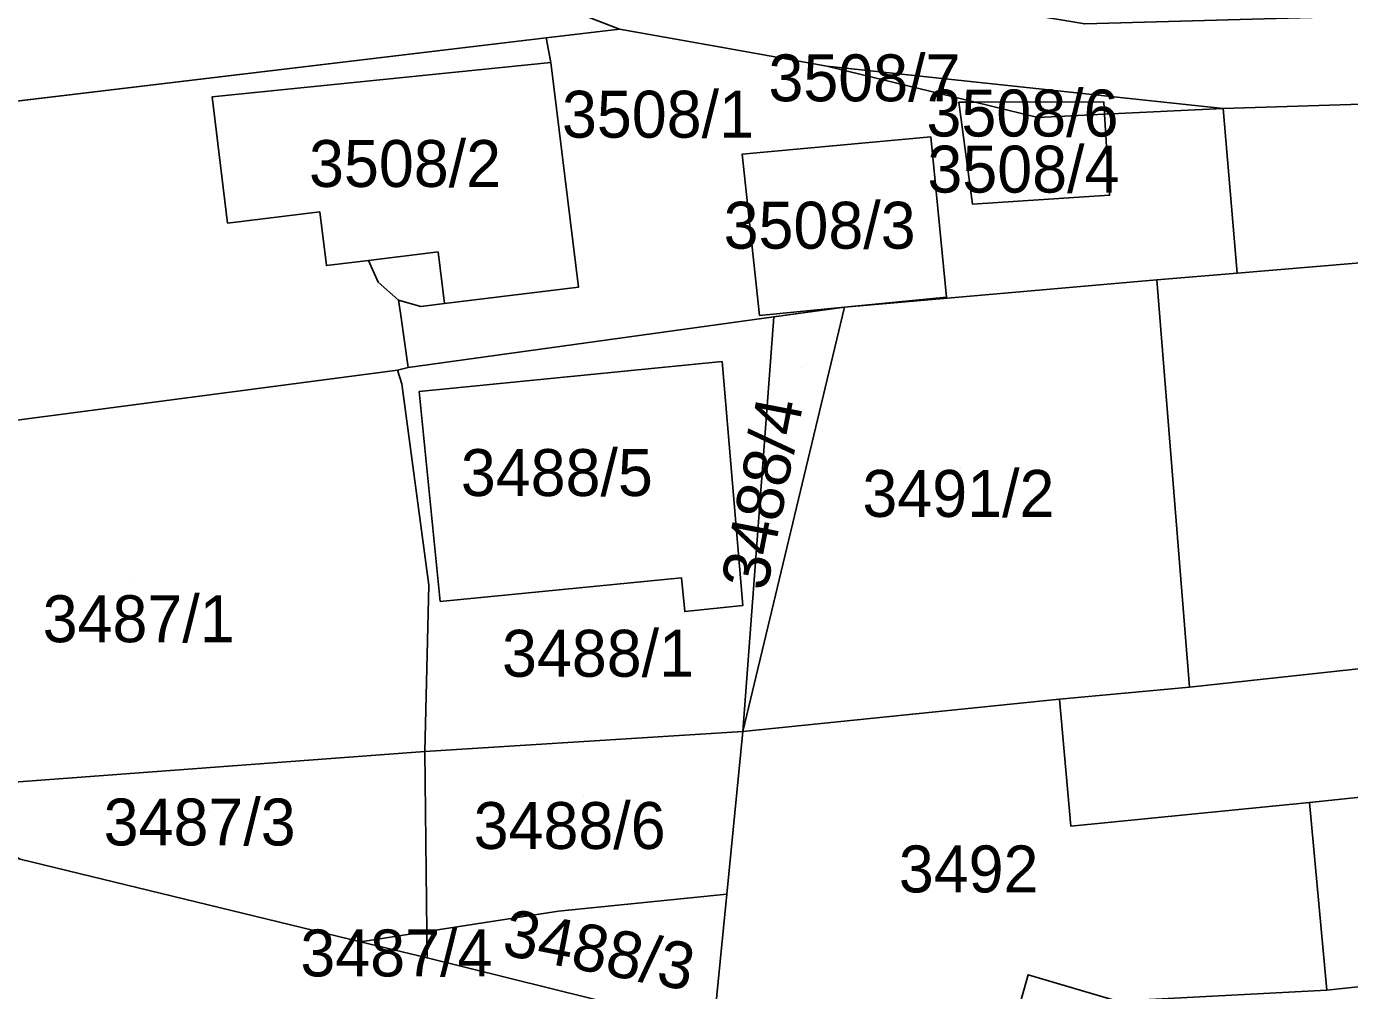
# Model space of a CAD drawing. Extents: x -262657 to -261595, y -1238015 to -1237156.
# Drawn here: x -262217.3 to -262160.9, y -1237493.9 to -1237452.8 of the extents above; entities that cross this region are included whole.
import ezdxf

# ---------------------------------------------------------------- set-up
doc = ezdxf.new("R2010")
doc.units = 0
for name, color, linetype in [('body_kn', 7, 'Continuous'), ('kladpar_druhypozemkov', 7, 'Continuous'), ('kladpar_hranice', 7, 'Continuous'), ('kladpar_parcelnecisla', 7, 'Continuous'), ('kladpar_plochy', 7, 'Continuous'), ('zappar_hrandruhpozemk', 7, 'Continuous')]:
    doc.layers.add(name, color=color, linetype=linetype)

msp = doc.modelspace()

# ---------------------------------------------------------------- linework, layer by layer
at = {"layer": 'body_kn'}
for p, q in [((-262192.05, -1237452.94), (-262192.05, -1237452.94)), ((-262195.18, -1237453.31), (-262195.18, -1237453.31)), ((-262195.18, -1237453.31), (-262195.18, -1237453.31)), ((-262187.73, -1237453.71), (-262187.73, -1237453.71)), ((-262194.98, -1237454.37), (-262194.98, -1237454.37)), ((-262194.98, -1237454.37), (-262194.98, -1237454.37)), ((-262183.22, -1237454.52), (-262183.22, -1237454.52)), ((-262183.22, -1237454.52), (-262183.22, -1237454.52)), ((-262209.41, -1237455.83), (-262209.41, -1237455.83)), ((-262177.59, -1237456.06), (-262177.59, -1237456.06)), ((-262177.59, -1237456.06), (-262177.59, -1237456.06)), ((-262176.89, -1237456.06), (-262176.89, -1237456.06)), ((-262171.42, -1237456.04), (-262171.42, -1237456.04)), ((-262171.42, -1237456.04), (-262171.42, -1237456.04)), ((-262171.39, -1237456.57), (-262171.39, -1237456.57)), ((-262166.33, -1237456.32), (-262166.33, -1237456.32)), ((-262166.33, -1237456.32), (-262166.33, -1237456.32)), ((-262174.23, -1237456.71), (-262174.23, -1237456.71)), ((-262178.78, -1237457.54), (-262178.78, -1237457.54)), ((-262186.82, -1237458.27), (-262186.82, -1237458.27)), ((-262186.82, -1237458.27), (-262186.82, -1237458.27)), ((-262171.17, -1237460.02), (-262171.17, -1237460.02)), ((-262177.01, -1237460.4), (-262177.01, -1237460.4)), ((-262204.82, -1237460.73), (-262204.82, -1237460.73)), ((-262208.75, -1237461.21), (-262208.75, -1237461.21)), ((-262202.75, -1237462.81), (-262202.75, -1237462.81)), ((-262202.75, -1237462.81), (-262202.75, -1237462.81)), ((-262199.77, -1237462.44), (-262199.77, -1237462.44)), ((-262204.54, -1237463.02), (-262204.54, -1237463.02)), ((-262165.74, -1237463.34), (-262165.74, -1237463.34)), ((-262202.33, -1237463.73), (-262202.33, -1237463.73)), ((-262193.8, -1237463.94), (-262193.8, -1237463.94)), ((-262169.15, -1237463.63), (-262169.15, -1237463.63)), ((-262201.46, -1237464.49), (-262201.46, -1237464.49)), ((-262178.12, -1237464.37), (-262178.12, -1237464.37)), ((-262201.38, -1237465.05), (-262201.38, -1237465.05)), ((-262200.52, -1237464.76), (-262200.52, -1237464.76)), ((-262199.5, -1237464.63), (-262199.5, -1237464.63)), ((-262182.46, -1237464.79), (-262182.46, -1237464.79)), ((-262182.46, -1237464.79), (-262182.46, -1237464.79)), ((-262186.08, -1237465.14), (-262186.08, -1237465.14)), ((-262185.48, -1237465.21), (-262185.48, -1237465.21)), ((-262201.05, -1237467.36), (-262201.05, -1237467.36)), ((-262187.68, -1237467.11), (-262187.68, -1237467.11)), ((-262201.51, -1237467.47), (-262201.51, -1237467.47)), ((-262201.51, -1237467.47), (-262201.51, -1237467.47)), ((-262201.33, -1237468.06), (-262201.33, -1237468.06)), ((-262200.58, -1237468.39), (-262200.58, -1237468.39)), ((-262189.41, -1237476.32), (-262189.41, -1237476.32)), ((-262200.18, -1237476.64), (-262200.18, -1237476.64)), ((-262199.69, -1237477.34), (-262199.69, -1237477.34)), ((-262199.69, -1237477.34), (-262199.69, -1237477.34)), ((-262186.8, -1237477.51), (-262186.8, -1237477.51)), ((-262189.27, -1237477.76), (-262189.27, -1237477.76)), ((-262167.76, -1237480.98), (-262167.76, -1237480.98)), ((-262173.3, -1237481.5), (-262173.3, -1237481.5)), ((-262186.79, -1237482.88), (-262186.79, -1237482.88)), ((-262186.79, -1237482.88), (-262186.79, -1237482.88)), ((-262200.34, -1237483.73), (-262200.34, -1237483.73)), ((-262162.65, -1237485.9), (-262162.65, -1237485.9)), ((-262172.82, -1237486.91), (-262172.82, -1237486.91)), ((-262187.47, -1237489.81), (-262187.47, -1237489.81)), ((-262194.65, -1237490.53), (-262194.65, -1237490.53)), ((-262194.65, -1237490.53), (-262194.65, -1237490.53)), ((-262200.26, -1237491.4), (-262200.26, -1237491.4)), ((-262203.08, -1237491.83), (-262203.08, -1237491.83)), ((-262203.08, -1237491.83), (-262203.08, -1237491.83)), ((-262200.25, -1237492.52), (-262200.25, -1237492.52)), ((-262174.64, -1237493.24), (-262174.64, -1237493.24)), ((-262161.92, -1237493.89), (-262161.92, -1237493.89)), ((-262161.92, -1237493.89), (-262161.92, -1237493.89))]:
    msp.add_line(p, q, dxfattribs=at)
at = {"layer": 'kladpar_druhypozemkov'}
for p, q in [((-262180.68, -1237454.95), (-262180.68, -1237454.95)), ((-262190.66, -1237456.11), (-262190.66, -1237456.11)), ((-262173.99, -1237456.3), (-262173.99, -1237456.3)), ((-262200.34, -1237457.91), (-262200.34, -1237457.91)), ((-262174.07, -1237458.24), (-262174.07, -1237458.24)), ((-262182.44, -1237460.43), (-262182.44, -1237460.43)), ((-262184.29, -1237467.37), (-262184.29, -1237467.37)), ((-262193.73, -1237470.88), (-262193.73, -1237470.88)), ((-262177.53, -1237471.67), (-262177.53, -1237471.67)), ((-262212.93, -1237476.36), (-262212.93, -1237476.36)), ((-262192.96, -1237478.63), (-262192.96, -1237478.63)), ((-262193.58, -1237485.59), (-262193.58, -1237485.59)), ((-262209.51, -1237486.32), (-262209.51, -1237486.32)), ((-262177.09, -1237488.16), (-262177.09, -1237488.16)), ((-262201.44, -1237491.98), (-262201.44, -1237491.98)), ((-262192.56, -1237491.88), (-262192.56, -1237491.88))]:
    msp.add_line(p, q, dxfattribs=at)
at = {"layer": 'kladpar_hranice'}
for p, q in [((-262183.22, -1237454.52), (-262166.33, -1237456.32)), ((-262176.89, -1237456.06), (-262183.22, -1237454.52)), ((-262183.22, -1237454.52), (-262176.89, -1237456.06)), ((-262177.59, -1237456.06), (-262176.89, -1237456.06)), ((-262176.89, -1237456.06), (-262171.42, -1237456.04)), ((-262171.42, -1237456.04), (-262171.39, -1237456.57)), ((-262166.33, -1237456.32), (-262171.39, -1237456.57)), ((-262171.39, -1237456.57), (-262166.33, -1237456.32))]:
    msp.add_line(p, q, dxfattribs=at)
for points in [[(-262230.34, -1237434.19), (-262221.46, -1237439.3), (-262209.51, -1237446.2), (-262192.05, -1237452.94), (-262195.18, -1237453.31), (-262242.2, -1237458.94), (-262242.94, -1237448.59), (-262237.36, -1237447.78), (-262237.65, -1237443.96)], [(-262137.3, -1237455.41), (-262166.33, -1237456.32), (-262183.22, -1237454.52), (-262187.73, -1237453.71), (-262192.05, -1237452.94), (-262209.51, -1237446.2), (-262221.46, -1237439.3), (-262220.93, -1237439.31), (-262218, -1237436.69), (-262214.52, -1237438.44), (-262207.07, -1237441.9), (-262193.17, -1237448.01), (-262184.15, -1237450.78), (-262180.7, -1237451.3), (-262172.23, -1237452.72), (-262144.2, -1237451.94)], [(-262195.18, -1237453.31), (-262192.05, -1237452.94), (-262187.73, -1237453.71), (-262183.22, -1237454.52)], [(-262254.6, -1237460.42), (-262242.2, -1237458.94), (-262195.18, -1237453.31), (-262194.98, -1237454.37), (-262209.41, -1237455.83), (-262208.75, -1237461.21), (-262204.82, -1237460.73), (-262204.54, -1237463.02), (-262202.75, -1237462.81), (-262202.33, -1237463.73), (-262201.46, -1237464.49), (-262201.38, -1237465.05), (-262201.05, -1237467.36), (-262201.51, -1237467.47), (-262251.24, -1237474.01), (-262254.6, -1237460.42)], [(-262185.48, -1237465.21), (-262201.05, -1237467.36), (-262201.38, -1237465.05), (-262201.46, -1237464.49), (-262200.52, -1237464.76), (-262199.5, -1237464.63), (-262193.8, -1237463.94), (-262194.98, -1237454.37), (-262195.18, -1237453.31)], [(-262194.98, -1237454.37), (-262193.8, -1237463.94), (-262199.5, -1237464.63), (-262200.52, -1237464.76), (-262201.46, -1237464.49), (-262202.33, -1237463.73), (-262202.75, -1237462.81), (-262204.54, -1237463.02), (-262204.82, -1237460.73), (-262208.75, -1237461.21), (-262209.41, -1237455.83), (-262194.98, -1237454.37)], [(-262166.33, -1237456.32), (-262137.3, -1237455.41), (-262124.74, -1237457.28), (-262120.3, -1237459.49), (-262143.93, -1237461.51), (-262165.74, -1237463.34), (-262166.33, -1237456.32)], [(-262171.39, -1237456.57), (-262171.17, -1237460.02), (-262177.01, -1237460.4), (-262177.59, -1237456.06)], [(-262176.89, -1237456.06), (-262177.59, -1237456.06), (-262177.01, -1237460.4), (-262171.17, -1237460.02), (-262171.39, -1237456.57)], [(-262171.39, -1237456.57), (-262171.42, -1237456.04), (-262176.89, -1237456.06)], [(-262171.39, -1237456.57), (-262174.23, -1237456.71), (-262176.89, -1237456.06)], [(-262176.89, -1237456.06), (-262174.23, -1237456.71), (-262171.39, -1237456.57)], [(-262166.33, -1237456.32), (-262165.74, -1237463.34), (-262169.15, -1237463.63), (-262182.46, -1237464.79), (-262185.48, -1237465.21)], [(-262186.82, -1237458.27), (-262178.78, -1237457.54), (-262178.12, -1237464.37), (-262182.46, -1237464.79), (-262186.08, -1237465.14), (-262186.82, -1237458.27)], [(-262186.08, -1237465.14), (-262182.46, -1237464.79), (-262178.12, -1237464.37), (-262178.78, -1237457.54), (-262186.82, -1237458.27), (-262186.08, -1237465.14)], [(-262135.5, -1237477.53), (-262159, -1237480.03), (-262167.76, -1237480.98), (-262169.15, -1237463.63), (-262165.74, -1237463.34), (-262143.93, -1237461.51), (-262143.12, -1237468.01), (-262138.13, -1237467.57), (-262137.27, -1237475.95), (-262135.55, -1237475.84), (-262135.51, -1237477.18), (-262135.5, -1237477.53)], [(-262182.46, -1237464.79), (-262169.15, -1237463.63), (-262167.76, -1237480.98), (-262173.3, -1237481.5), (-262186.79, -1237482.88), (-262182.46, -1237464.79)], [(-262186.79, -1237482.88), (-262185.48, -1237465.21), (-262182.46, -1237464.79), (-262186.79, -1237482.88)], [(-262201.51, -1237467.47), (-262201.05, -1237467.36), (-262185.48, -1237465.21), (-262186.79, -1237482.88), (-262200.34, -1237483.73)], [(-262199.69, -1237477.34), (-262200.58, -1237468.39), (-262187.68, -1237467.11), (-262186.8, -1237477.51), (-262189.27, -1237477.76), (-262189.41, -1237476.32), (-262199.69, -1237477.34)], [(-262199.69, -1237477.34), (-262189.41, -1237476.32), (-262189.27, -1237477.76), (-262186.8, -1237477.51), (-262187.68, -1237467.11), (-262200.58, -1237468.39), (-262199.69, -1237477.34)], [(-262227.97, -1237485.78), (-262233.77, -1237484.32), (-262249.82, -1237480.64), (-262251.24, -1237474.01), (-262201.51, -1237467.47), (-262201.33, -1237468.06), (-262200.18, -1237476.64), (-262200.34, -1237483.73), (-262222.8, -1237485.4), (-262227.97, -1237485.78)], [(-262200.34, -1237483.73), (-262200.18, -1237476.64), (-262201.33, -1237468.06), (-262201.51, -1237467.47)], [(-262100.07, -1237473.74), (-262098.36, -1237475.95), (-262108.93, -1237477.01), (-262108.19, -1237482.75), (-262110.64, -1237482.99), (-262139.61, -1237485.8), (-262139.74, -1237483.44), (-262150.33, -1237484.6), (-262162.65, -1237485.9), (-262172.82, -1237486.91), (-262173.3, -1237481.5), (-262167.76, -1237480.98), (-262159, -1237480.03), (-262135.5, -1237477.53), (-262127.63, -1237476.72), (-262121.33, -1237476.07), (-262111.63, -1237475.04), (-262100.07, -1237473.74)], [(-262176.23, -1237498.85), (-262188.04, -1237495.55), (-262187.47, -1237489.81), (-262186.79, -1237482.88), (-262173.3, -1237481.5), (-262172.82, -1237486.91), (-262162.65, -1237485.9), (-262161.92, -1237493.89), (-262170.83, -1237494.36), (-262174.64, -1237493.24), (-262176.23, -1237498.85)], [(-262194.65, -1237490.53), (-262200.26, -1237491.4), (-262200.34, -1237483.73), (-262186.79, -1237482.88), (-262187.47, -1237489.81), (-262194.65, -1237490.53)], [(-262203.08, -1237491.83), (-262217.58, -1237488.31), (-262222.8, -1237485.4), (-262200.34, -1237483.73), (-262200.26, -1237491.4), (-262203.08, -1237491.83)], [(-262154.86, -1237504.09), (-262172.44, -1237499.78), (-262176.23, -1237498.85), (-262174.64, -1237493.24), (-262170.83, -1237494.36), (-262161.92, -1237493.89), (-262162.65, -1237485.9), (-262150.33, -1237484.6), (-262139.74, -1237483.44), (-262139.61, -1237485.8), (-262139.16, -1237493.69), (-262154.25, -1237495.79), (-262154.86, -1237504.09)], [(-262233.77, -1237484.32), (-262227.97, -1237485.78), (-262217.58, -1237488.31), (-262203.08, -1237491.83), (-262200.25, -1237492.52), (-262188.04, -1237495.55), (-262176.23, -1237498.85), (-262172.44, -1237499.78), (-262154.86, -1237504.09), (-262127.96, -1237510.84), (-262123.16, -1237511.93), (-262108.89, -1237515.33), (-262096.16, -1237518.4), (-262086.35, -1237520.76), (-262075.41, -1237523.56), (-262071.48, -1237524.52), (-262067.34, -1237525.53), (-262049.86, -1237529.82), (-262034.62, -1237534.07), (-262030.05, -1237535.39)], [(-262188.04, -1237495.55), (-262200.25, -1237492.52), (-262200.26, -1237491.4), (-262194.65, -1237490.53), (-262187.47, -1237489.81), (-262188.04, -1237495.55)], [(-262203.08, -1237491.83), (-262200.26, -1237491.4), (-262200.25, -1237492.52), (-262203.08, -1237491.83)]]:
    msp.add_lwpolyline(points, dxfattribs=at)
at = {"layer": 'kladpar_plochy'}
for p, q in [((-262209.51, -1237446.2), (-262192.05, -1237452.94)), ((-262192.05, -1237452.94), (-262195.18, -1237453.31)), ((-262195.18, -1237453.31), (-262192.05, -1237452.94)), ((-262192.05, -1237452.94), (-262187.73, -1237453.71)), ((-262195.18, -1237453.31), (-262242.2, -1237458.94)), ((-262194.98, -1237454.37), (-262195.18, -1237453.31)), ((-262187.73, -1237453.71), (-262183.22, -1237454.52)), ((-262193.8, -1237463.94), (-262194.98, -1237454.37)), ((-262183.22, -1237454.52), (-262176.89, -1237456.06)), ((-262176.89, -1237456.06), (-262177.59, -1237456.06)), ((-262177.59, -1237456.06), (-262177.01, -1237460.4)), ((-262171.39, -1237456.57), (-262166.33, -1237456.32)), ((-262171.17, -1237460.02), (-262171.39, -1237456.57)), ((-262166.33, -1237456.32), (-262165.74, -1237463.34)), ((-262178.78, -1237457.54), (-262186.82, -1237458.27)), ((-262178.12, -1237464.37), (-262178.78, -1237457.54)), ((-262186.82, -1237458.27), (-262186.08, -1237465.14)), ((-262177.01, -1237460.4), (-262171.17, -1237460.02)), ((-262165.74, -1237463.34), (-262169.15, -1237463.63)), ((-262199.5, -1237464.63), (-262193.8, -1237463.94)), ((-262169.15, -1237463.63), (-262182.46, -1237464.79)), ((-262201.38, -1237465.05), (-262201.46, -1237464.49)), ((-262201.46, -1237464.49), (-262200.52, -1237464.76)), ((-262182.46, -1237464.79), (-262178.12, -1237464.37)), ((-262201.05, -1237467.36), (-262201.38, -1237465.05)), ((-262200.52, -1237464.76), (-262199.5, -1237464.63)), ((-262186.08, -1237465.14), (-262182.46, -1237464.79)), ((-262182.46, -1237464.79), (-262185.48, -1237465.21)), ((-262185.48, -1237465.21), (-262201.05, -1237467.36)), ((-262201.05, -1237467.36), (-262185.48, -1237465.21)), ((-262185.48, -1237465.21), (-262186.79, -1237482.88)), ((-262201.51, -1237467.47), (-262201.05, -1237467.36)), ((-262187.68, -1237467.11), (-262200.58, -1237468.39)), ((-262186.8, -1237477.51), (-262187.68, -1237467.11)), ((-262201.33, -1237468.06), (-262201.51, -1237467.47)), ((-262200.18, -1237476.64), (-262201.33, -1237468.06)), ((-262200.58, -1237468.39), (-262199.69, -1237477.34)), ((-262199.69, -1237477.34), (-262189.41, -1237476.32)), ((-262189.41, -1237476.32), (-262189.27, -1237477.76)), ((-262200.34, -1237483.73), (-262200.18, -1237476.64)), ((-262189.27, -1237477.76), (-262186.8, -1237477.51)), ((-262186.79, -1237482.88), (-262200.34, -1237483.73))]:
    msp.add_line(p, q, dxfattribs=at)
for points in [[(-262137.3, -1237455.41), (-262166.33, -1237456.32), (-262183.22, -1237454.52), (-262187.73, -1237453.71), (-262192.05, -1237452.94), (-262209.51, -1237446.2), (-262221.46, -1237439.3), (-262220.93, -1237439.31), (-262218, -1237436.69), (-262214.52, -1237438.44), (-262207.07, -1237441.9), (-262193.17, -1237448.01), (-262184.15, -1237450.78), (-262180.7, -1237451.3), (-262172.23, -1237452.72), (-262144.2, -1237451.94)], [(-262274.37, -1237475.76), (-262249.82, -1237480.64), (-262233.77, -1237484.32), (-262227.97, -1237485.78), (-262217.58, -1237488.31), (-262203.08, -1237491.83), (-262200.25, -1237492.52), (-262188.04, -1237495.55), (-262176.23, -1237498.85), (-262172.44, -1237499.78), (-262154.86, -1237504.09), (-262127.96, -1237510.84), (-262123.16, -1237511.93), (-262108.89, -1237515.33), (-262096.16, -1237518.4), (-262086.35, -1237520.76), (-262075.41, -1237523.56), (-262071.48, -1237524.52), (-262067.34, -1237525.53), (-262049.86, -1237529.82), (-262034.62, -1237534.07), (-262030.05, -1237535.39)]]:
    msp.add_lwpolyline(points, dxfattribs=at)
for points in [[(-262254.6, -1237460.42), (-262242.2, -1237458.94), (-262195.18, -1237453.31), (-262194.98, -1237454.37), (-262209.41, -1237455.83), (-262208.75, -1237461.21), (-262204.82, -1237460.73), (-262204.54, -1237463.02), (-262202.75, -1237462.81), (-262202.33, -1237463.73), (-262201.46, -1237464.49), (-262201.38, -1237465.05), (-262201.05, -1237467.36), (-262201.51, -1237467.47), (-262251.24, -1237474.01)], [(-262194.98, -1237454.37), (-262193.8, -1237463.94), (-262199.5, -1237464.63), (-262200.52, -1237464.76), (-262201.46, -1237464.49), (-262202.33, -1237463.73), (-262202.75, -1237462.81), (-262204.54, -1237463.02), (-262204.82, -1237460.73), (-262208.75, -1237461.21), (-262209.41, -1237455.83)], [(-262183.22, -1237454.52), (-262166.33, -1237456.32), (-262171.39, -1237456.57), (-262171.42, -1237456.04), (-262176.89, -1237456.06)], [(-262166.33, -1237456.32), (-262137.3, -1237455.41), (-262124.74, -1237457.28), (-262120.3, -1237459.49), (-262143.93, -1237461.51), (-262165.74, -1237463.34)], [(-262177.59, -1237456.06), (-262176.89, -1237456.06), (-262174.23, -1237456.71), (-262171.39, -1237456.57), (-262171.17, -1237460.02), (-262177.01, -1237460.4)], [(-262171.42, -1237456.04), (-262171.39, -1237456.57), (-262174.23, -1237456.71), (-262176.89, -1237456.06)], [(-262186.82, -1237458.27), (-262178.78, -1237457.54), (-262178.12, -1237464.37), (-262182.46, -1237464.79), (-262186.08, -1237465.14)], [(-262135.5, -1237477.53), (-262159, -1237480.03), (-262167.76, -1237480.98), (-262169.15, -1237463.63), (-262165.74, -1237463.34), (-262143.93, -1237461.51), (-262143.12, -1237468.01), (-262138.13, -1237467.57), (-262137.27, -1237475.95), (-262135.55, -1237475.84), (-262135.51, -1237477.18)], [(-262182.46, -1237464.79), (-262169.15, -1237463.63), (-262167.76, -1237480.98), (-262173.3, -1237481.5), (-262186.79, -1237482.88)], [(-262186.79, -1237482.88), (-262185.48, -1237465.21), (-262182.46, -1237464.79)], [(-262199.69, -1237477.34), (-262200.58, -1237468.39), (-262187.68, -1237467.11), (-262186.8, -1237477.51), (-262189.27, -1237477.76), (-262189.41, -1237476.32)], [(-262227.97, -1237485.78), (-262233.77, -1237484.32), (-262249.82, -1237480.64), (-262251.24, -1237474.01), (-262201.51, -1237467.47), (-262201.33, -1237468.06), (-262200.18, -1237476.64), (-262200.34, -1237483.73), (-262222.8, -1237485.4)], [(-262100.07, -1237473.74), (-262098.36, -1237475.95), (-262108.93, -1237477.01), (-262108.19, -1237482.75), (-262110.64, -1237482.99), (-262139.61, -1237485.8), (-262139.74, -1237483.44), (-262150.33, -1237484.6), (-262162.65, -1237485.9), (-262172.82, -1237486.91), (-262173.3, -1237481.5), (-262167.76, -1237480.98), (-262159, -1237480.03), (-262135.5, -1237477.53), (-262127.63, -1237476.72), (-262121.33, -1237476.07), (-262111.63, -1237475.04)], [(-262176.23, -1237498.85), (-262188.04, -1237495.55), (-262187.47, -1237489.81), (-262186.79, -1237482.88), (-262173.3, -1237481.5), (-262172.82, -1237486.91), (-262162.65, -1237485.9), (-262161.92, -1237493.89), (-262170.83, -1237494.36), (-262174.64, -1237493.24)], [(-262194.65, -1237490.53), (-262200.26, -1237491.4), (-262200.34, -1237483.73), (-262186.79, -1237482.88), (-262187.47, -1237489.81)], [(-262203.08, -1237491.83), (-262217.58, -1237488.31), (-262222.8, -1237485.4), (-262200.34, -1237483.73), (-262200.26, -1237491.4)], [(-262154.86, -1237504.09), (-262172.44, -1237499.78), (-262176.23, -1237498.85), (-262174.64, -1237493.24), (-262170.83, -1237494.36), (-262161.92, -1237493.89), (-262162.65, -1237485.9), (-262150.33, -1237484.6), (-262139.74, -1237483.44), (-262139.61, -1237485.8), (-262139.16, -1237493.69), (-262154.25, -1237495.79)], [(-262188.04, -1237495.55), (-262200.25, -1237492.52), (-262200.26, -1237491.4), (-262194.65, -1237490.53), (-262187.47, -1237489.81)], [(-262203.08, -1237491.83), (-262200.26, -1237491.4), (-262200.25, -1237492.52)]]:
    msp.add_lwpolyline(points, close=True, dxfattribs=at)
at = {"layer": 'zappar_hrandruhpozemk'}
for p, q in [((-262202.75, -1237462.81), (-262199.77, -1237462.44)), ((-262199.77, -1237462.44), (-262199.5, -1237464.63)), ((-262161.92, -1237493.89), (-262149.42, -1237492.59))]:
    msp.add_line(p, q, dxfattribs=at)

# ---------------------------------------------------------------- texts
at = {"layer": 'kladpar_parcelnecisla'}
for s, p in [('3508/7', (-262185.703, -1237456.02)), ('3508/1', (-262194.501, -1237457.57)), ('3508/6', (-262178.97, -1237457.52)), ('3508/2', (-262205.277, -1237459.67)), ('3508/4', (-262178.93, -1237459.91)), ('3508/3', (-262187.613, -1237462.3)), ('3488/5', (-262198.81, -1237472.84)), ('3491/2', (-262181.7, -1237473.73)), ('3487/1', (-262216.627, -1237479.07)), ('3488/1', (-262197.056, -1237480.54)), ('3487/3', (-262214.029, -1237487.73)), ('3488/6', (-262198.265, -1237487.88)), ('3492', (-262180.149, -1237489.73)), ('3487/4', (-262205.647, -1237493.31))]:
    msp.add_text(s, height=2, dxfattribs=at).set_placement(p)
for s, rotation, p in [('3488/4', 79, (-262185.775, -1237476.924)), ('3488/3', 349, (-262197.114, -1237492.375))]:
    msp.add_text(s, height=2, rotation=rotation, dxfattribs=at).set_placement(p)

doc.saveas('drawing.dxf')
